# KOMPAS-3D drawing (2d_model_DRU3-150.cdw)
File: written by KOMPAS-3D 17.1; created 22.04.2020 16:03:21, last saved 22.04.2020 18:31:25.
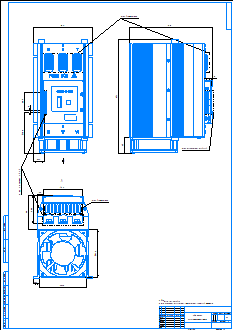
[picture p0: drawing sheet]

Sheet 1: A1, portrait

Title block, sheet 1: name: DRU3-150 / Габаритный чертеж; sheets: 1; sheet format: A1; stored path: E:\Марк\DRU3\DRU3-XX\2d_model_DRU3-200.cdw

Views: Вид по стрелке 4
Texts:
  Пользователь Windows
  ·зЙИ
  НвїЗЈЁ7.27Ј©
  ИэПаЅУПЯ¶ЛЧУ
  ЛДПаЅУПЯ¶ЛЧУ
  РЎПЯВ·°еЈЁ0Ј©
  Гж°еЧйєП(7.27)
  ВЭДё
  M4ВЭЛї
  ВЭДёС№Ж¬
  ВЭЛї
  µжЖ¬
  M8ВЭЛїЧйєП
  M4ВЭЛї(0)
  M3-10ЖЅН·ВЭЛї
  M3ВЭЛї(0)
  M4ВЭЛї(і¤)
Dimensions and other numbers on the sheet: 1:1; 1; 200AЙўИИЖч(0); 200AІа°е(0); 200AЦ§јЬ(0); 200AєуёЗ(1); 200AHHT3µчЅЪїЄ№ШPCB(0); 200AєуёЗ(0); 200AИэПаµзБ¦µчХыЖч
